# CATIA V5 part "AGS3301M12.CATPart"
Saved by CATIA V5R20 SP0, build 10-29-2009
Part number: AGS3301M12
Definition: NONE
Nomenclature: AGS3301M12
Source: Unknown
Description: AGS3301M12
Bounding box of the stored display mesh (mm): x -20 to 25, y -10.811 to 10.811, z -8.8 to 8.8
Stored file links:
  C:\Users\Utente\Desktop\IO LAVORO\3D X SITO CF\X SITO\PLASTICA\AGS\AGS3301M12.CATPart
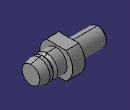
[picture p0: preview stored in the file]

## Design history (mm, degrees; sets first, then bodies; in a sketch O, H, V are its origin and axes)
Body1 "AGS3301M12" (main body)
  Solid1: solid without history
